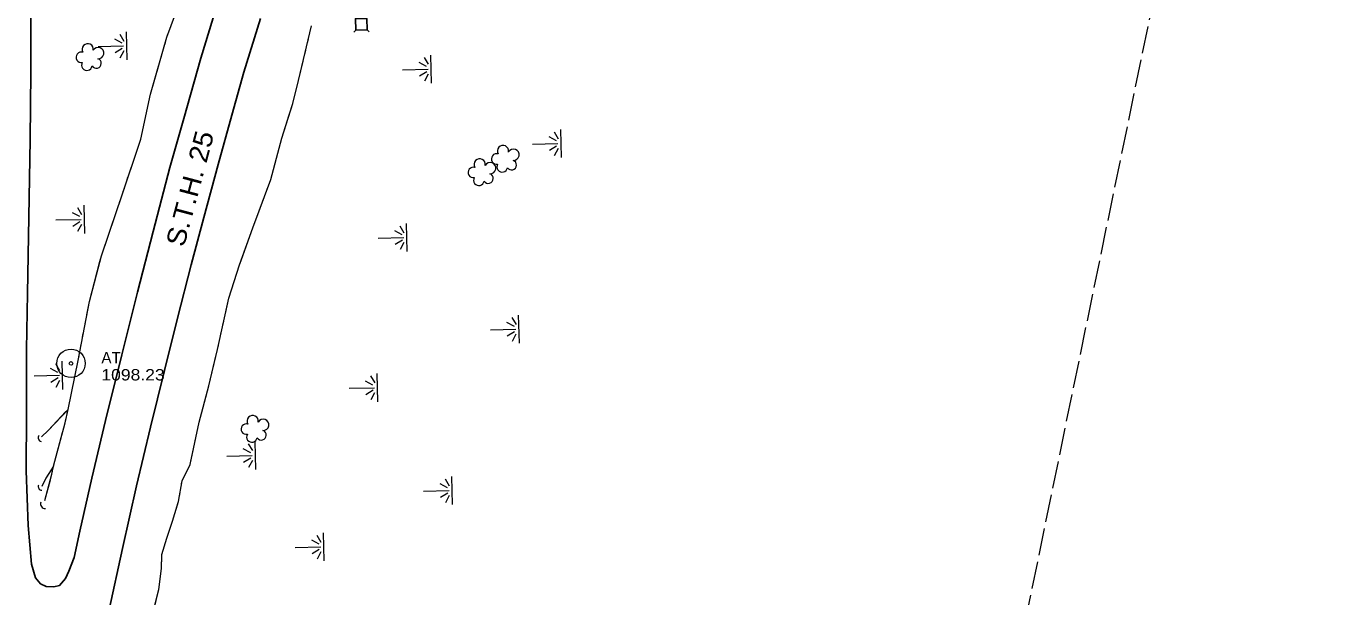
# Model space of a CAD drawing. Extents: x 296527 to 298902, y 45711 to 46924.
# Drawn here: x 297706 to 298395, y 46136 to 46436 of the extents above; entities that cross this region are included whole.
import ezdxf

# ---------------------------------------------------------------- set-up
doc = ezdxf.new("R2010")
doc.units = 0
doc.header["$LTSCALE"] = 2.4
doc.linetypes.add('LONG_DASHED', pattern=[7.5, 6, -1.5])
for name, color, linetype, lineweight in [('11', 7, 'Continuous', 25), ('15', 7, 'Continuous', 13), ('18', 7, 'Continuous', 13), ('19', 7, 'Continuous', 13), ('21', 7, 'Continuous', 25), ('4', 7, 'Continuous', 13), ('6', 7, 'Continuous', 13)]:
    doc.layers.add(name, color=color, linetype=linetype, lineweight=lineweight)

msp = doc.modelspace()

# ---------------------------------------------------------------- linework, layer by layer
at = {"layer": '11'}
for points in [[(297730.886, 46156.37), (297728.161, 46149.242), (297726.35, 46145.219), (297723.228, 46141.65), (297720.111, 46140.925), (297716.225, 46141.059), (297713.173, 46142.484), (297710.595, 46145.583), (297708.456, 46152.791), (297706.705, 46173.162), (297705.612, 46202.055), (297705.765, 46232.466), (297705.802, 46265.915), (297706.401, 46295.476), (297706.964, 46335.689), (297707.677, 46376.558), (297708.054, 46412.102), (297708.117, 46447.507)], [(297730.886, 46156.37), (297733.884, 46170.262), (297740.233, 46198.102), (297747.487, 46228.471), (297756, 46263.215), (297764.277, 46296.208), (297772.504, 46328.057), (297781.37, 46361.816), (297788.724, 46387.745), (297797.637, 46419.407), (297806.038, 46447.108)], [(297749.131, 46127.998), (297756.356, 46161.052), (297763.676, 46194.148), (297771.062, 46225.043), (297778.529, 46254.926), (297785.346, 46282.401), (297792.578, 46310.534), (297799.243, 46335.537), (297806.714, 46363.511), (297814.035, 46389.44), (297820.298, 46412.015), (297829.138, 46440.368)]]:
    msp.add_lwpolyline(points, dxfattribs=at)
at = {"layer": '15'}
for centre, radius, start, end in [((297714.104, 46219.509), 2.167, 147.79712, 254.03668), ((297713.978, 46193.818), 2.039, 159.11755, 265.35712), ((297715.791, 46184.753), 2.636, 163.37431, 269.61388)]:
    msp.add_arc(centre, radius, start, end, dxfattribs=at)
at = {"layer": '18'}
for centre, radius, start, end in [((297738.053, 46424.11), 2.974, 349.94487, 211.17875), ((297734.693, 46419.916), 2.777, 72.91576, 280.68875), ((297743.569, 46422.15), 2.975, 267.59569, 150.56896), ((297737.609, 46415.779), 2.783, 149.59278, 350.60382), ((297742.562, 46416.72), 2.611, 212.30092, 70.23353), ((297956.866, 46370.528), 2.974, 349.94487, 211.17875), ((297962.382, 46368.568), 2.975, 267.59569, 150.56896), ((297944.598, 46363.463), 2.974, 349.94487, 211.17875), ((297953.506, 46366.334), 2.777, 72.91576, 280.68875), ((297961.375, 46363.138), 2.611, 212.30092, 70.23353), ((297941.238, 46359.269), 2.777, 72.91576, 280.68875), ((297949.107, 46356.073), 2.611, 212.30092, 70.23353), ((297950.114, 46361.503), 2.975, 267.59569, 150.56896), ((297956.422, 46362.197), 2.783, 149.59278, 350.60382), ((297944.154, 46355.132), 2.783, 149.59278, 350.60382), ((297821.641, 46224.026), 2.777, 72.91576, 280.68875), ((297825.001, 46228.22), 2.974, 349.94487, 211.17875), ((297830.517, 46226.26), 2.975, 267.59569, 150.56896), ((297824.557, 46219.889), 2.783, 149.59278, 350.60382), ((297829.51, 46220.83), 2.611, 212.30092, 70.23353)]:
    msp.add_arc(centre, radius, start, end, dxfattribs=at)
at = {"layer": '19'}
for p, q in [((297855.261, 46433.56), (297855.725, 46435.525)), ((297756.174, 46427.32), (297752.269, 46429.422)), ((297754.897, 46432.074), (297757.08, 46428.444)), ((297758.818, 46418.53), (297758.442, 46433.32)), ((297778.417, 46425.779), (297778.974, 46427.693)), ((297780.157, 46431.498), (297780.847, 46433.368)), ((297853.87, 46427.666), (297854.334, 46429.631)), ((297743.564, 46425.57), (297756.98, 46425.91)), ((297756.245, 46424.516), (297752.452, 46422.219)), ((297755.212, 46419.703), (297757.207, 46423.44)), ((297776.747, 46420.037), (297777.304, 46421.951)), ((297852.479, 46421.773), (297852.943, 46423.737)), ((297915.298, 46419.867), (297917.481, 46416.237)), ((297919.219, 46406.323), (297918.843, 46421.113)), ((297903.965, 46413.363), (297917.381, 46413.703)), ((297916.575, 46415.113), (297912.67, 46417.215)), ((297916.646, 46412.309), (297912.853, 46410.012)), ((297915.613, 46407.496), (297917.608, 46411.233)), ((297983.742, 46380.61), (297985.925, 46376.98)), ((297987.663, 46367.066), (297987.287, 46381.856)), ((297972.409, 46374.106), (297985.825, 46374.446)), ((297985.019, 46375.856), (297981.114, 46377.958)), ((297985.09, 46373.052), (297981.297, 46370.755)), ((297984.057, 46368.239), (297986.052, 46371.976)), ((297756.725, 46349.144), (297757.358, 46351.034)), ((297758.626, 46354.814), (297759.259, 46356.703)), ((297832.398, 46349.889), (297833.102, 46351.781)), ((297834.502, 46355.567), (297835.024, 46357.517)), ((297754.813, 46343.478), (297755.452, 46345.366)), ((297830.285, 46344.214), (297830.989, 46346.105)), ((297733.876, 46335.941), (297729.971, 46338.043)), ((297732.599, 46340.695), (297734.782, 46337.065)), ((297736.52, 46327.151), (297736.144, 46341.941)), ((297721.266, 46334.191), (297734.682, 46334.531)), ((297733.947, 46333.137), (297730.154, 46330.84)), ((297732.914, 46328.324), (297734.909, 46332.061)), ((297902.499, 46331.115), (297904.682, 46327.485)), ((297906.42, 46317.571), (297906.044, 46332.361)), ((297891.166, 46324.611), (297904.582, 46324.951)), ((297903.776, 46326.361), (297899.871, 46328.463)), ((297903.847, 46323.557), (297900.054, 46321.26)), ((297902.814, 46318.744), (297904.809, 46322.481)), ((297961.561, 46282.795), (297963.744, 46279.165)), ((297965.482, 46269.251), (297965.106, 46284.041)), ((297736.449, 46278.335), (297736.821, 46280.294)), ((297808, 46273.052), (297808.429, 46275.025)), ((297809.286, 46278.97), (297809.715, 46280.942)), ((297950.228, 46276.291), (297963.644, 46276.631)), ((297962.838, 46278.041), (297958.933, 46280.143)), ((297962.909, 46275.237), (297959.116, 46272.94)), ((297734.216, 46266.585), (297734.588, 46268.544)), ((297735.332, 46272.46), (297735.704, 46274.419)), ((297806.713, 46267.134), (297807.142, 46269.107)), ((297961.876, 46270.424), (297963.871, 46274.161)), ((297722.363, 46253.754), (297718.458, 46255.856)), ((297721.086, 46258.508), (297723.269, 46254.878)), ((297725.007, 46244.964), (297724.631, 46259.754)), ((297709.753, 46252.004), (297723.169, 46252.344)), ((297722.434, 46250.95), (297718.641, 46248.653)), ((297721.401, 46246.137), (297723.396, 46249.874)), ((297888.343, 46247.244), (297884.438, 46249.346)), ((297887.066, 46251.998), (297889.249, 46248.368)), ((297890.987, 46238.454), (297890.611, 46253.244)), ((297875.733, 46245.494), (297889.149, 46245.834)), ((297888.414, 46244.44), (297884.621, 46242.143)), ((297887.381, 46239.627), (297889.376, 46243.364)), ((297726.356, 46228.436), (297726.63, 46229.68)), ((297727.179, 46232.168), (297727.453, 46233.412)), ((297720.003, 46204.421), (297724.764, 46222.27)), ((297725.42, 46224.732), (297725.749, 46225.962)), ((297823.937, 46211.532), (297820.032, 46213.634)), ((297822.66, 46216.286), (297824.843, 46212.656)), ((297826.581, 46202.742), (297826.205, 46217.532)), ((297811.327, 46209.782), (297824.743, 46210.122)), ((297824.008, 46208.728), (297820.215, 46206.431)), ((297822.975, 46203.915), (297824.97, 46207.652)), ((297718.791, 46198.693), (297718.995, 46199.436)), ((297719.345, 46200.934), (297719.488, 46201.69)), ((297719.773, 46203.204), (297719.916, 46203.96)), ((297789.744, 46200.768), (297790.635, 46202.579)), ((297715.432, 46186.441), (297718.384, 46197.208)), ((297927.662, 46193.003), (297923.757, 46195.105)), ((297926.385, 46197.757), (297928.568, 46194.127)), ((297930.306, 46184.213), (297929.93, 46199.003)), ((297786.499, 46189.224), (297786.835, 46191.214)), ((297915.052, 46191.253), (297928.468, 46191.593)), ((297927.733, 46190.199), (297923.94, 46187.902)), ((297926.7, 46185.386), (297928.695, 46189.123)), ((297860, 46163.329), (297856.095, 46165.431)), ((297858.723, 46168.083), (297860.906, 46164.453)), ((297862.644, 46154.539), (297862.268, 46169.329)), ((297847.39, 46161.579), (297860.806, 46161.919)), ((297860.071, 46160.525), (297856.278, 46158.228)), ((297859.038, 46155.712), (297861.033, 46159.449))]:
    msp.add_line(p, q, dxfattribs=at)
for points in [[(297727.661, 46234.355), (297732.98, 46260.083), (297738.903, 46291.249), (297745.297, 46315.358), (297756.148, 46347.424), (297765.976, 46376.737), (297771.06, 46400.488), (297779.797, 46430.522), (297789.42, 46456.6), (297797.023, 46481.408), (297804.603, 46509.862), (297813.358, 46538.762), (297823.513, 46568.595), (297833.773, 46597.545), (297845.531, 46622.563), (297856.504, 46652.912), (297867.391, 46677.903), (297881.799, 46714.74), (297897.082, 46758.62), (297911.1, 46787.728), (297927.574, 46820.51), (297941.355, 46857.021), (297955.912, 46885.019), (297969.251, 46907.237)], [(297772.657, 46127.931), (297775.522, 46139.511), (297776.952, 46150.575), (297777.152, 46157.897), (297779.792, 46166.532), (297782.797, 46175.445), (297785.942, 46185.927), (297787.772, 46196.756), (297792.029, 46205.415), (297796.824, 46227.66), (297801.85, 46246.769), (297806.441, 46265.883), (297812.344, 46293.032), (297818.061, 46310.519), (297825.01, 46330.047), (297834.476, 46355.471), (297840.3, 46377.227), (297846.169, 46395.623), (297849.168, 46407.743), (297855.933, 46436.406)], [(297768.437, 46388.236), (297771.06, 46400.488), (297775.633, 46416.209)], [(297844.222, 46389.52), (297846.169, 46395.623), (297849.168, 46407.743), (297851.552, 46417.843)], [(297760.526, 46360.483), (297765.976, 46376.737), (297768.437, 46388.236)], [(297836.068, 46361.417), (297840.3, 46377.227), (297844.222, 46389.52)], [(297744.476, 46312.261), (297745.297, 46315.358), (297753.535, 46339.701)], [(297818.912, 46312.909), (297825.01, 46330.047), (297828.876, 46340.43)], [(297737.565, 46284.21), (297738.903, 46291.249), (297744.476, 46312.261)], [(297810.573, 46284.887), (297812.344, 46293.032), (297818.061, 46310.519), (297818.912, 46312.909)], [(297727.661, 46234.355), (297732.98, 46260.083), (297733.471, 46262.669)], [(297798.704, 46234.808), (297801.85, 46246.769), (297805.797, 46263.203)], [(297720.003, 46204.421), (297726.106, 46227.302), (297727.661, 46234.355), (297717.207, 46223.287), (297713.648, 46220.02)], [(297792.214, 46206.272), (297796.824, 46227.66), (297798.704, 46234.808)], [(297726.575, 46233.205), (297717.207, 46223.287), (297713.648, 46220.02)], [(297715.432, 46186.441), (297719.211, 46200.223), (297720.003, 46204.421), (297715.92, 46198.083), (297713.944, 46193.823)], [(297719.423, 46203.521), (297715.92, 46198.083), (297713.944, 46193.823)], [(297787.508, 46195.194), (297787.772, 46196.756), (297787.963, 46197.145)], [(297777.136, 46157.325), (297777.152, 46157.897), (297779.792, 46166.532), (297782.797, 46175.445), (297785.743, 46185.264)], [(297772.796, 46128.492), (297775.522, 46139.511), (297776.952, 46150.575), (297777.136, 46157.325)]]:
    msp.add_lwpolyline(points, dxfattribs=at)
at = {"layer": '21'}
for p, q in [((297879.257, 46434.273), (297878.223, 46433.188)), ((297886.342, 46433.393), (297885.254, 46434.426))]:
    msp.add_line(p, q, dxfattribs=at)
msp.add_lwpolyline([(297885.254, 46434.426), (297885.102, 46440.425), (297879.105, 46440.272), (297879.257, 46434.273)], close=True, dxfattribs=at)
at = {"layer": '4', "linetype": 'LONG_DASHED'}
msp.add_lwpolyline([(298394.638, 46912.137), (298194.005, 45938.519), (298192.285, 45793.642)], dxfattribs=at)
at = {"layer": '6'}
for radius in [7.5, 0.96]:
    msp.add_circle((297729.242, 46258.636), radius, dxfattribs=at)

# ---------------------------------------------------------------- texts
at = {"layer": '11', "width": 1.1}
msp.add_text('S.T.H. 25', height=10, rotation=75.074, dxfattribs=at).set_placement((297788.75, 46319.467))
at = {"layer": '6'}
msp.add_text('AT', height=6, dxfattribs=at).set_placement((297745.242, 46258.636))
at = {"layer": '6', "width": 1.15}
msp.add_text('1098.23', height=6, dxfattribs=at).set_placement((297745.242, 46249.636))

doc.saveas('drawing.dxf')
